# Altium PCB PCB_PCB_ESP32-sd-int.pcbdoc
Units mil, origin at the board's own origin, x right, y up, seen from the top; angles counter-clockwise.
Board outline 4345.15 x 3059.05 mil, 4 copper layers (Top Layer, Inner1, Inner2, Bottom Layer); 53 components, 39 nets, 233 pads, 78 vias.
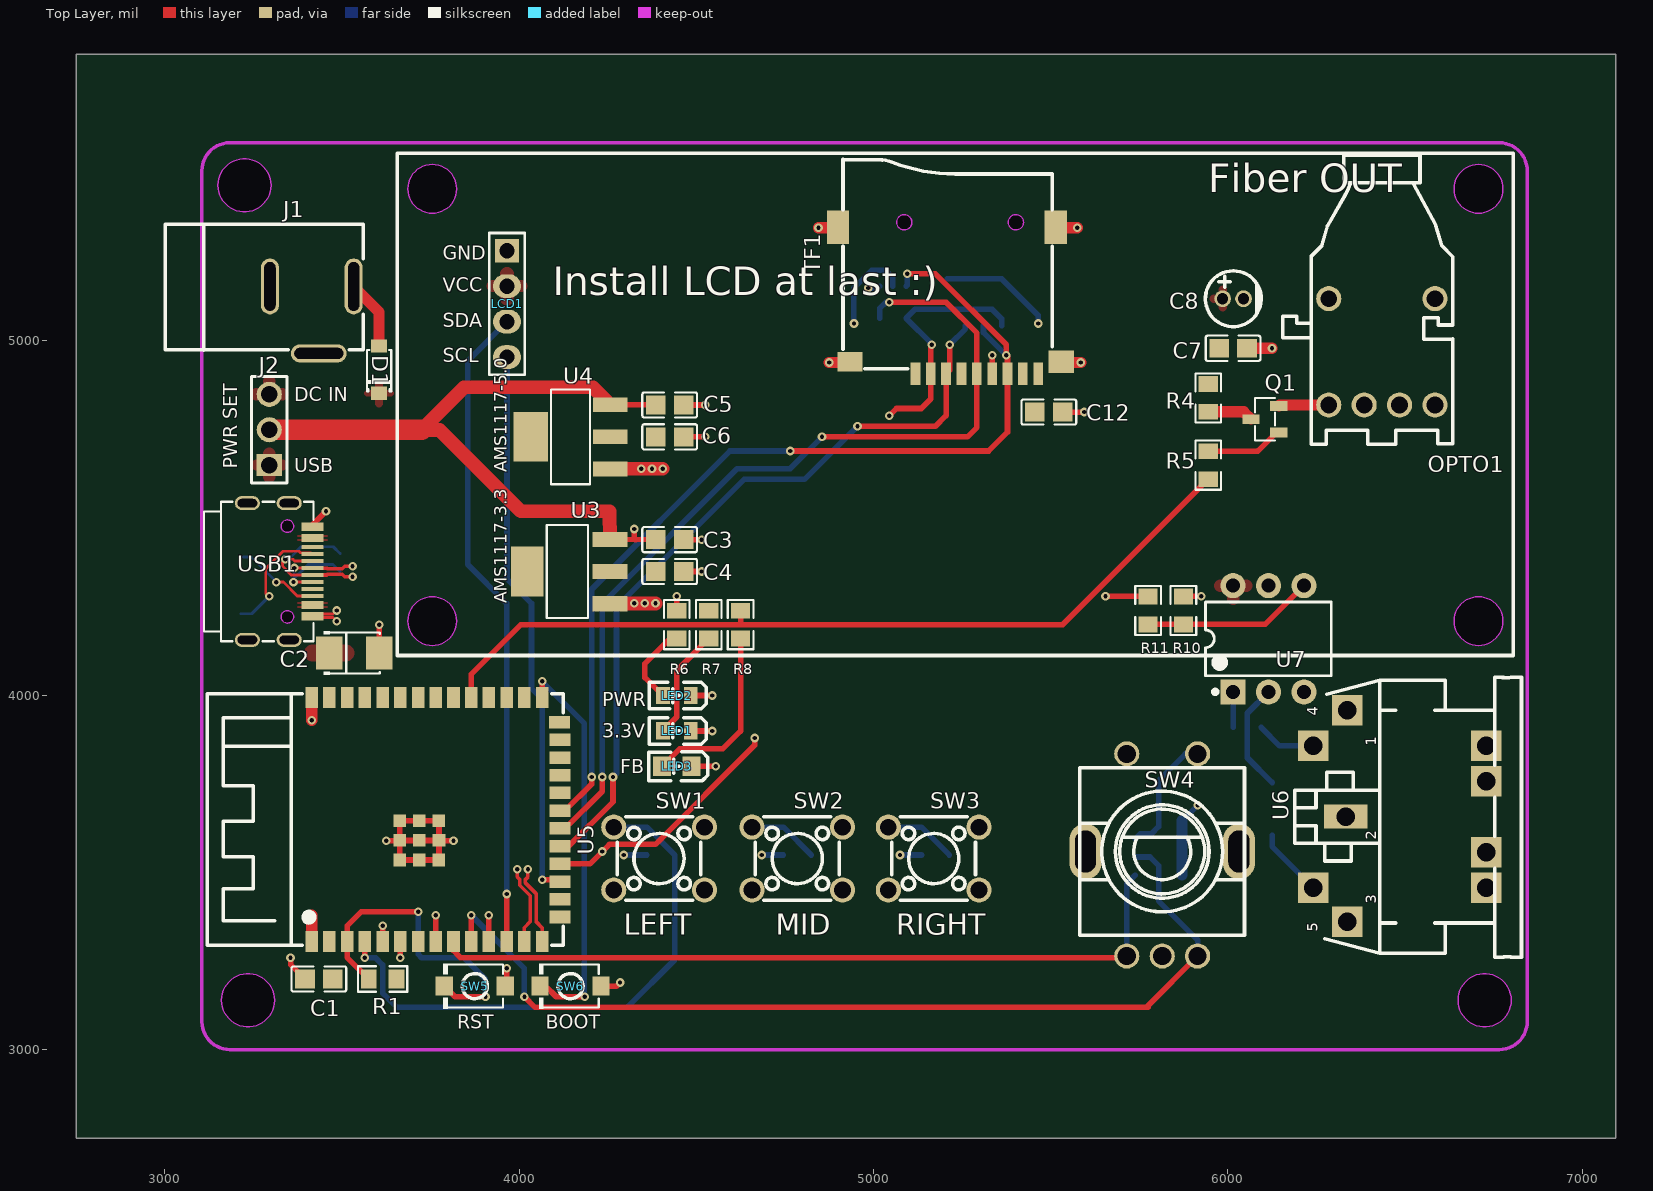
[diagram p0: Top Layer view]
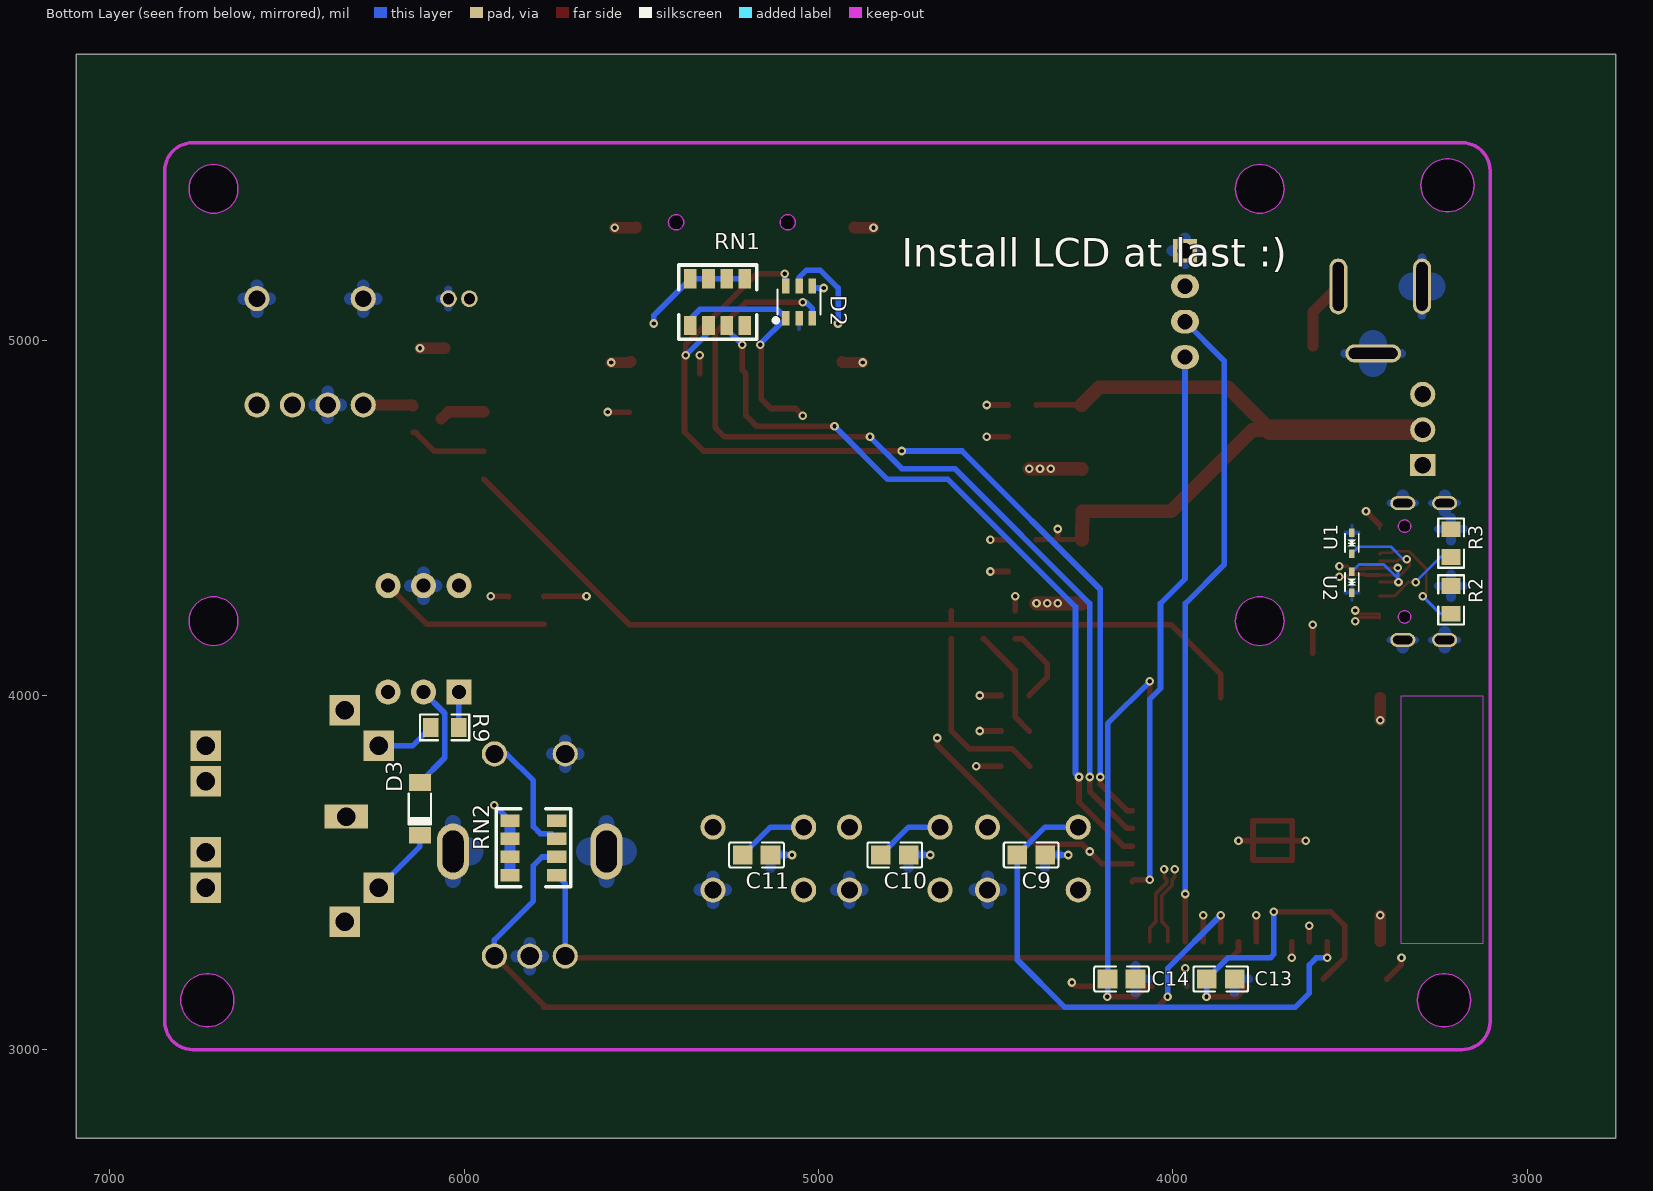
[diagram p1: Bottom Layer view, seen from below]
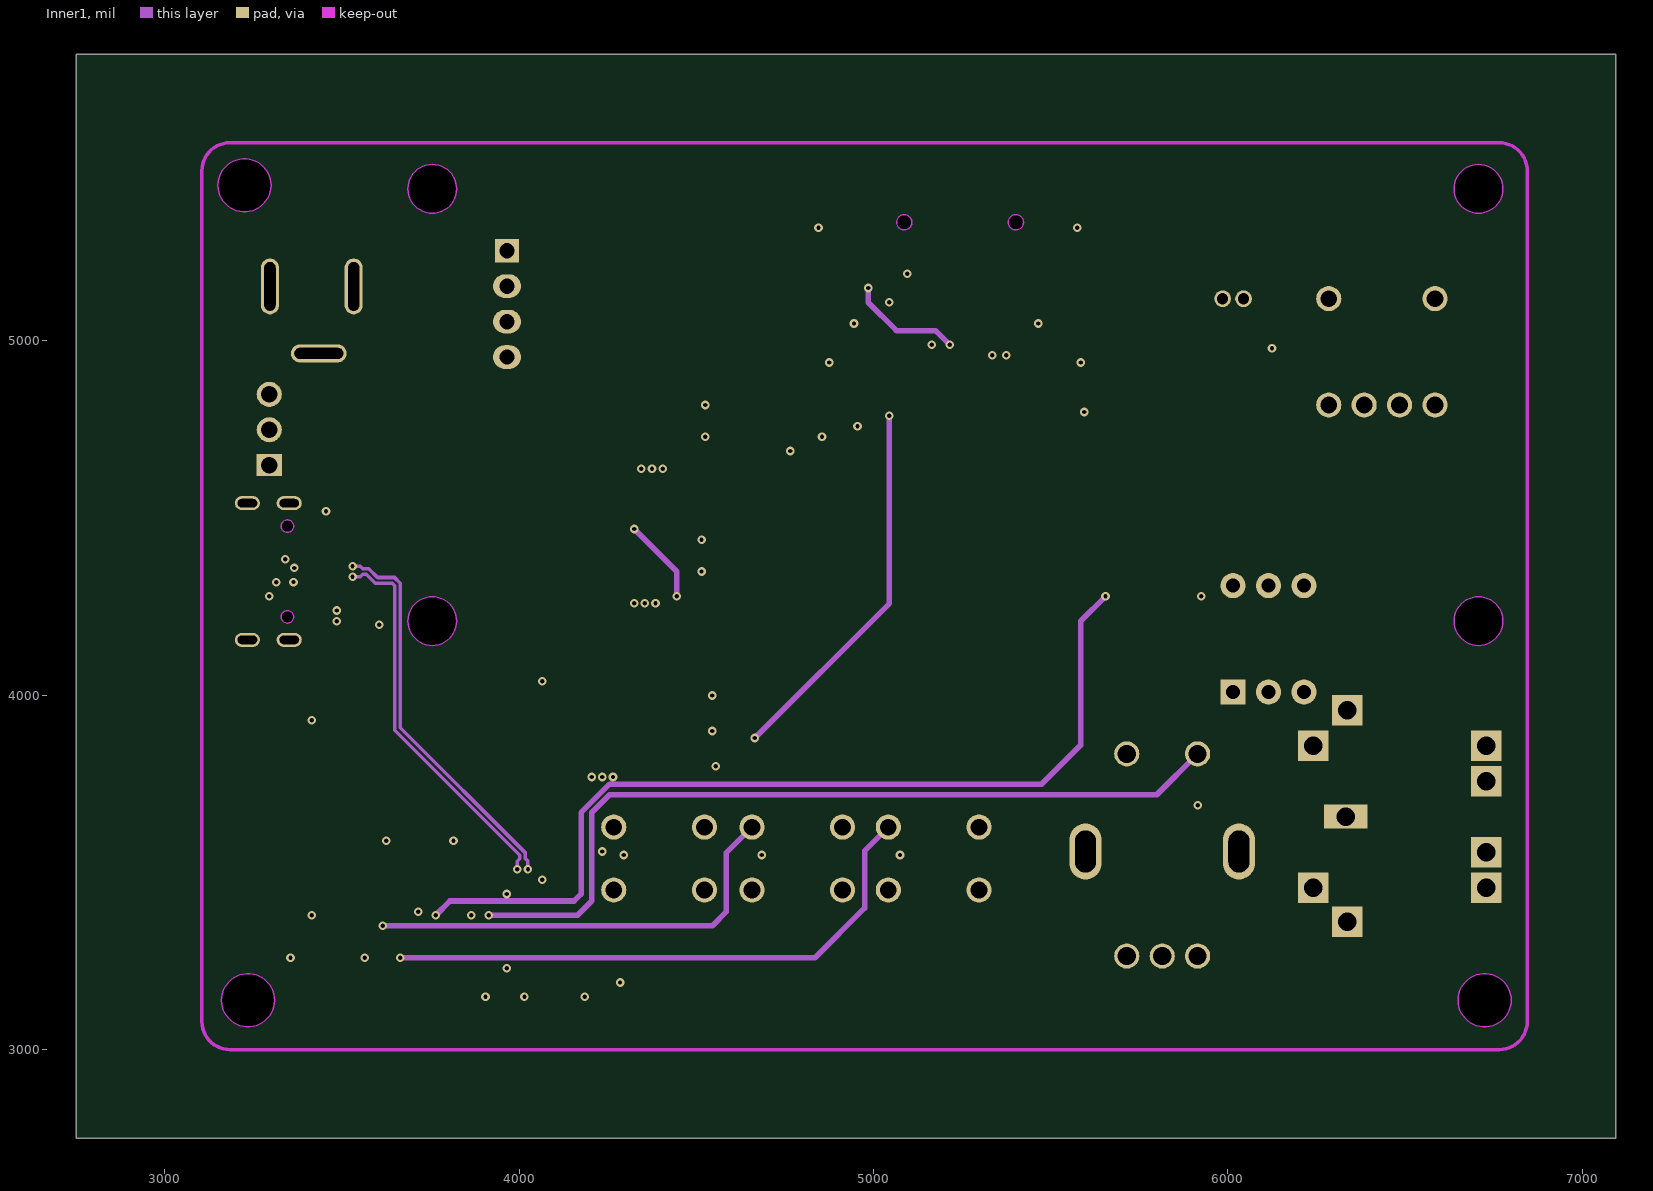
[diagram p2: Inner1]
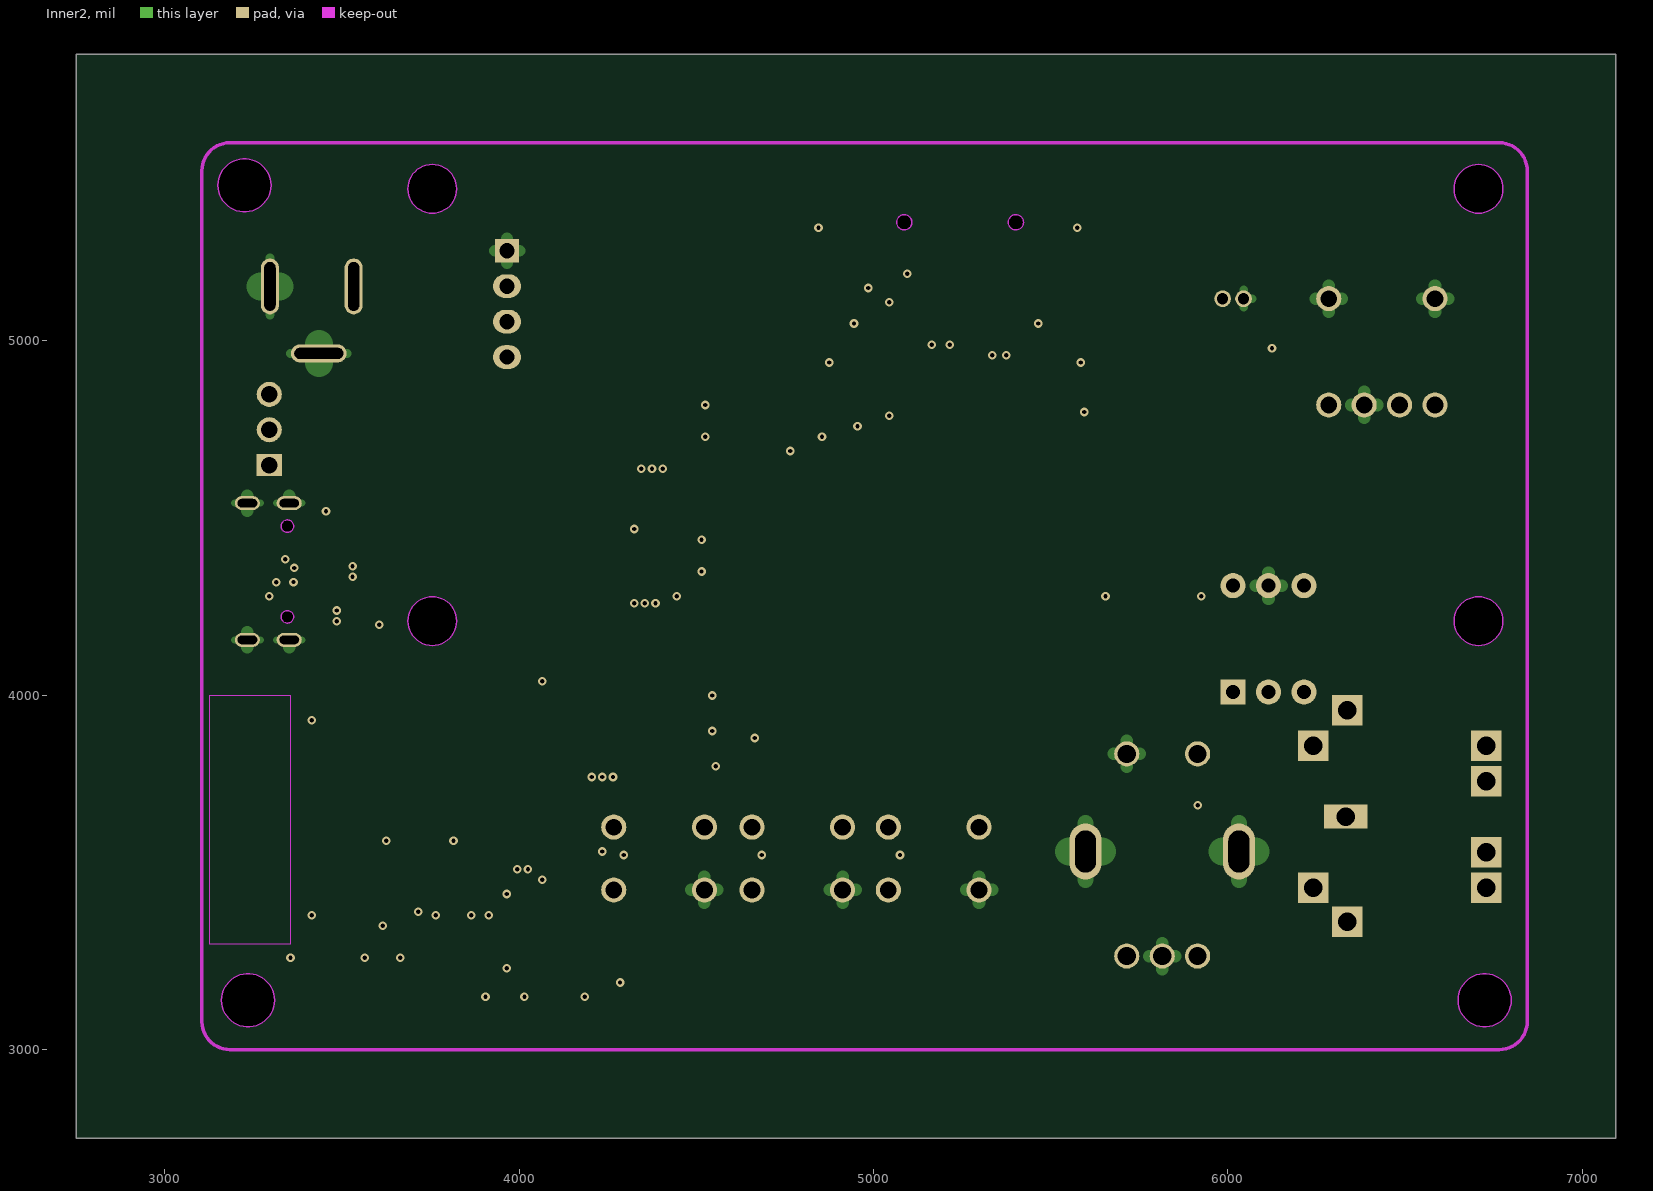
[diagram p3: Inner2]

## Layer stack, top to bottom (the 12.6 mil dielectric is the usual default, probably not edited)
Top Layer: signal copper (thickness not stored)
Dielectric: dielectric 12.6, FR-4, Dk 4.8
Inner1: signal copper (thickness not stored)
Dielectric: dielectric 12.6, FR-4, Dk 4.8
Inner2: signal copper (thickness not stored)
Dielectric: dielectric 12.6, FR-4, Dk 4.8
Bottom Layer: signal copper (thickness not stored)

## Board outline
7095.15,2750 2750,2750 2750,5809.05 7095.15,5809.05
cut-out: 3300,5439.05 cw(c3225,5439.05) 3150,5439.05 cw(c3225,5439.05)
cut-out: 6799.99,3139.05 cw(c6724.99,3139.05) 6649.99,3139.05 cw(c6724.99,3139.05)
cut-out: 3310,3139.05 cw(c3235,3139.05) 3160,3139.05 cw(c3235,3139.05)

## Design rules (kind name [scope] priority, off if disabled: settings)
BoardOutlineClearance Default [All] p0: genericclearance=10 ignorepadtopadclearanceinfootprint=FALSE except(0: Region-CutoutEdge Arc-SplitContinuation Track-SplitContinuation SMDPad-SplitContinuation THPad-SplitContinuation Via-SplitContinuation Fill-SplitContinuation Poly-SplitContinuation Region-SplitContinuation Text-SplitContinuation; 3.9: Track-OutlineEdge SMDPad-OutlineEdge THPad-OutlineEdge Via-OutlineEdge Fill-OutlineEdge Region-OutlineEdge Poly-OutlineEdge Text-OutlineEdge Track-CutoutEdge SMDPad-CutoutEdge THPad-CutoutEdge Via-CutoutEdge Fill-CutoutEdge)
Clearance Default [(InNet('GND') OR InNet('VBUS') OR InNet('J2_3') OR InNet('+3.3V') OR InNet('+5V') OR InNet('ENC_A') OR InNet('ENC_B') OR InNet('ENC_SW') OR InNet('U6_5') OR InNet('U7_2') OR InNet('U6_4') OR InNet('U7_1') OR InNet('BTN3') OR InNet('BTN2') OR InNet('BTN1') OR InNet('SCLK') OR InNet('CLK') OR InNet('MOSI') OR InNet('SDA') OR InNet('CHIP_EN') OR InNet('MISO') OR InNet('USB_P') OR InNet('USB_N') OR InNet('CS') OR InNet('USB1_A5') OR InNet('USB1_B5') OR InNet('IO0') OR InNet('VSET') OR InNet('MIDI_RX') OR InNet('VIN') OR InNet('OPTO1_1') OR InNet('Q1_3') OR InNet('Q1_1') OR InNet('LED1_2') OR InNet('LED3_1') OR InNet('LED2_2') OR InNet('U7_4') OR InNet('FB') OR InNet('MT'))] p1: gap=7 ignorepadtopadclearanceinfootprint=FALSE except(0: Region-Region; 3.9: Track-Track Track-SMDPad SMDPad-SMDPad Track-THPad SMDPad-THPad THPad-THPad Track-Via SMDPad-Via THPad-Via Via-Via Track-Fill SMDPad-Fill THPad-Fill Via-Fill Fill-Fill Track-Region SMDPad-Region THPad-Region Via-Region Fill-Region Track-Poly SMDPad-Poly THPad-Poly Via-Poly Fill-Poly Region-Poly Poly-Poly Track-Text SMDPad-Text THPad-Text Via-Text Fill-Text Region-Text Poly-Text Text-Text Track-Sheet SMDPad-Sheet THPad-Sheet Via-Sheet Fill-Sheet Region-Sheet Poly-Sheet Text-Sheet Track-Hole SMDPad-Hole THPad-Hole Via-Hole Fill-Hole Region-Hole Poly-Hole Text-Hole Sheet-Hole)
DiffPairsRouting differentialPair [All] p1: maxuncoupledlength=10 minlimit=6 maxlimit=6 mostfreqgap=6 toplayer_minwidth=5 toplayer_prefwidth=10 toplayer_maxwidth=100 bottomlayer_minwidth=5 bottomlayer_prefwidth=10 bottomlayer_maxwidth=100 midlayer1_minwidth=5 midlayer1_prefwidth=10 midlayer1_maxwidth=100 midlayer2_minwidth=5 midlayer2_prefwidth=10 midlayer2_maxwidth=100
PasteMaskExpansion Common [All] p1: expansion=0
PlaneConnect Default [All] p1: planeconnectstyle=Relief reliefexpansion=20 reliefentries=4 reliefconductorwidth=0 reliefairgap=10
PolygonConnect Default [All] p1: connectstyle=Relief reliefentries=4 reliefconductorwidth=0 polygonreliefangle="90 Angle" airgapwidth=10
PolygonConnect gge9877 [All] p1: connectstyle=Relief reliefentries=4 reliefconductorwidth=0 polygonreliefangle="90 Angle" airgapwidth=10
PolygonConnect gge9877(1) [All] p1: connectstyle=Relief reliefentries=4 reliefconductorwidth=0 polygonreliefangle="90 Angle" airgapwidth=10
PolygonConnect gge17314 [All] p1: connectstyle=Relief reliefentries=4 reliefconductorwidth=0 polygonreliefangle="90 Angle" airgapwidth=10
PolygonConnect gge17404 [All] p1: connectstyle=Relief reliefentries=4 reliefconductorwidth=0 polygonreliefangle="90 Angle" airgapwidth=10
PolygonConnect gge17428 [All] p1: connectstyle=Direct reliefentries=4 reliefconductorwidth=0 polygonreliefangle="90 Angle" airgapwidth=7.87
PolygonConnect gge21029 [All] p1: connectstyle=Direct reliefentries=4 reliefconductorwidth=0 polygonreliefangle="90 Angle" airgapwidth=10
RoutingVias Default [All] p1: viastyle="Through Hole" holewidth=12.008 minholewidth=12.008 maxholewidth=2362 width=24.016 minwidth=24.016 maxwidth=3938
SolderMaskExpansion Common [All] p1: useseparateexpansions=TRUE expansion=2 expansionbottom=2
Width Default [All] p1: maxlimit=1000 minlimit=10 preferedwidth=10

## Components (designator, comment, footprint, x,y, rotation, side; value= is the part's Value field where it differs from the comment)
C1 "100nF" C0805 3435,3199.05 r0 top
C2 "10uF" CAP-SMD_L3.2-W2.8-FD 3535,4119.05 r0 top
C3 "10uF" C0805 4425,4439.05 r180 top
C4 "10uF" C0805 4425,4349.05 r180 top
C5 "10uF" C0805 4425,4819.05 r180 top
C6 "10uF" C0805 4425,4729.05 r180 top
C7 "100nF" C0805 6014.99,4979.05 r0 top
C8 "10uF" CAP-TH_BD4.0-P1.50-D0.8-FD 6014.99,5119.05 r0 top
C9 "100nF" C0805 4400,3549.05 r0 bottom
C10 "100nF" C0805 4785,3549.05 r0 bottom
C11 "100nF" C0805 5175,3549.05 r0 bottom
C12 "100nF" C0805 5495,4799.05 r0 top
C13 "100nF" C0805 3865,3199.05 r0 bottom
C14 "100nF" C0805 4145,3199.05 r0 bottom
D1 "DSS34" SOD-123_L2.8-W1.8-LS3.7-RD 3605,4919.05 r90 top
D2 "BV-SRV05-4" SOT-23-6_L2.9-W1.6-P0.95-LS2.8-BL 5055,5109.05 r180 bottom
D3 "1N4148-1206D" LL-34_L3.5-W1.5-R-RD 6124.99,3679.05 r90 bottom
J1 "9V Battery" DC-IN-TH_DC-5520-1 3415,5059.05 r0 top
J2 "Power settings" HDR-TH_3P-P2.54-V-M-1 3295,4749.05 r90 top
LCD1 "I2CLCD16X2" I2CLCD16X2 3755,4209.05 r0 top locked
LED1 "0805 SF-RED" LED0805-RD_RED 4445.03,3899.05 r180 top
LED2 "SF-RED" LED0805-RD_RED 4445.03,3999.05 r180 top
LED3 "YLED0805G" LED0805-FD-GREEN 4444.95,3799.1 r0 top
OPTO1 "FT10MHNR_C17216617" CONN-TH_HFBR-1521Z 6434.99,4969.05 r180 top
Q1 "SS8050S" SOT-23-3_L2.9-W1.3-P0.95-LS2.4-BR 6104.99,4779.05 r0 top
R1 "10kΩ" R0805 3615,3199.05 r0 top
R2 "5.1kΩ" R0805 3215,4269.05 r270 bottom
R3 "5.1kΩ" R0805 3215,4429.05 r270 bottom
R4 "33Ω" R0805 5945,4839.05 r90 top
R5 "470Ω" R0805 5945,4649.05 r90 top
R6 "10kΩ" R0805 4445,4199.05 r90 top
R7 "1.3kΩ" R0805 4535,4199.05 r90 top
R8 "2.2kΩ" R0805 4625,4199.05 r270 top
R9 "220Ω" R0805 6054.99,3909.05 r180 bottom
R10 "180Ω" R0805 5874.99,4239.05 r270 top
R11 "47Ω" R0805 5775,4239.05 r90 top
RN1 "10kΩ" RES-ARRAY-SMD_1206-8P-L5.1-W3.1-BL 5285,5109.05 r180 bottom
RN2 "10kΩ" RES-ARRAY-SMD_1206-8P-L5.1-W3.1-BL 5805,3569.05 r90 bottom
SW1 "TC-6610-18.0" SW-TH_4P-L6.0-W6.0-P4.50-LS6.5 4395,3539.05 r0 top
SW2 "TC-6610-18.0" SW-TH_4P-L6.0-W6.0-P4.50-LS6.5 4785,3539.05 r0 top
SW3 "TC-6610-18.0" SW-TH_4P-L6.0-W6.0-P4.50-LS6.5 5170,3539.05 r0 top
SW4 "EC11E18244A5" SW-TH_EC11E18244A5 5815,3549.05 r0 top
SW5 "TS-1088-AR02016" SW-SMD_L3.9-W3.0-P4.45 3875,3179.05 r180 top
SW6 "TS-1088-AR02016" SW-SMD_L3.9-W3.0-P4.45 4145,3179.05 r180 top
TF1 "SD" TF-SMD_TF-15-15 5215,5114.05 r90 top
U1 "LESD5D5.0CT1G_C5246195" SOD-523_L1.2-W0.8-LS1.6-BI 3495,4429.05 r270 bottom
U2 "LESD5D5.0CT1G_C5246195" SOD-523_L1.2-W0.8-LS1.6-BI 3495,4319.05 r90 bottom
U3 "AMS1117-3.3" SOT-223-3_L6.5-W3.4-P2.30-LS7.0-BR 4140.04,4349.05 r0 top
U4 "AMS1117-5.0" SOT-223_L6.5-W3.5-P2.30-LS7.0-BR 4145,4729.05 r0 top
U5 "ESP32-S3-WROOM-1(N8R8)" WIRELM-SMD_ESP32-S3-WROOM-1 3765,3649.05 r90 top
U6 "MIDIJACK" CP-2350 6484.99,3659.05 r90 top
U7 "H11L1" DIP-6_L8.5-W6.4-P2.54-LS7.6-BL 6114.99,4159.05 r0 top
USB1 "MUP-U20409-2" USB-C-SMD_MUP-U20409-2 3325,4349.05 r270 top

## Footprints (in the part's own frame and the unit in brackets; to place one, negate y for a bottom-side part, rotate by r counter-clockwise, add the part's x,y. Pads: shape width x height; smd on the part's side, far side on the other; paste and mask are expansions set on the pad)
C0805 [mm]
  rect 1.41x1.35 smd: 1(-1,0) 2(1,0)
  silkscreen extent -1.96,-0.9 1.96,0.9
CAP-SMD_L3.2-W2.8-FD [mm]
  rect 1.9x2.376 smd: 1(-1.799,0) 2(1.799,0)
  silkscreen extent -2.21,-1.55 1.83,1.55
CAP-TH_BD4.0-P1.50-D0.8-FD [mm]
  round 1.2 hole 0.8: 1(-0.75,0) 2(0.75,0)
  silkscreen extent -1.98,-2 2.06,2
CONN-TH_HFBR-1521Z [mm]
  round 1.8 hole 1.2: 1(3.81,3.81) 2(1.27,3.81) 3(-1.27,3.81) 4(-3.81,3.81) 5(-3.81,-3.81) 8(3.81,-3.81)
  silkscreen extent -5.08,-14.11 7.11,6.61
CP-2350 [mil]
  rect 86x86 hole 52: 1(297.99,148) 3(-298.01,148) 4(197.99,244) 5(-202.01,244) PE(-102.01,-244) PE1(-202.01,-244) PE2(197.99,-244) PE@(97.99,-244)
  rect 67.7x121.9 hole 52: 2(-2.01,152)
  silkscreen extent -398,-344 391,296
DC-IN-TH_DC-5520-1 [mm]
  oval 4x1.3 hole 0.8 slot 3.5 at 0 deg copper offset 0,0: 2(0.5,-2.4)
  oval 1.3x4 hole 0.8 slot 3.5 at 90 deg: 3(-3,2.4) 4(3,2.4)
  silkscreen extent -10.5,-2.16 3.7,6.85
DIP-6_L8.5-W6.4-P2.54-LS7.6-BL [mm]
  rect 1.8x1.8 hole 1: 1(-2.54,-3.81)
  round 1.8 hole 1: 2(0,-3.81) 3(2.54,-3.81) 4(2.54,3.81) 5(0,3.81) 6(-2.54,3.81)
  silkscreen extent -4.52,-3.95 4.5,2.65
HDR-TH_3P-P2.54-V-M-1 [mm]
  rect 1.575x1.8 hole 1.2: 1(-2.54,0)
  round 1.8 hole 1.2: 2(0,0) 3(2.54,0)
  silkscreen extent -3.81,-1.27 3.81,1.27
I2CLCD16X2 [mm]
  rect 1.7x1.7 hole 1.1: 1(5.359,26.549)
  oval 2x1.7 hole 1.1: 2(5.359,24.009) 3(5.359,21.469) 4(5.359,18.929)
  Board Outline Layer circle w0.005: c75,30.988 r1.75
  Board Outline Layer circle w0.005: c75,0 r1.75
  Board Outline Layer circle w0.005: c0,0 r1.75
  Board Outline Layer circle w0.005: c0,30.988 r1.75
  Board Outline Layer region: 76.75,30.988 76.577,30.229 76.091,29.62 75.389,29.282 74.61,29.282 73.909,29.62 73.423,30.229 73.25,30.988 73.25,30.988 73.423,31.747 73.909,32.356 74.61,32.694 75.389,32.694 76.091,32.356 76.577,31.747 76.75,30.988
  Board Outline Layer region: 76.75,0 76.577,-0.759 76.091,-1.368 75.389,-1.706 74.61,-1.706 73.909,-1.368 73.423,-0.759 73.25,0 73.25,0 73.423,0.759 73.909,1.368 74.61,1.706 75.389,1.706 76.091,1.368 76.577,0.759 76.75,0
  Board Outline Layer region: 1.75,0 1.577,-0.759 1.091,-1.368 0.389,-1.706 -0.389,-1.706 -1.091,-1.368 -1.577,-0.759 -1.75,0 -1.75,0 -1.577,0.759 -1.091,1.368 -0.389,1.706 0.389,1.706 1.091,1.368 1.577,0.759 1.75,0
  Board Outline Layer region: 1.75,30.988 1.577,30.229 1.091,29.62 0.389,29.282 -0.389,29.282 -1.091,29.62 -1.577,30.229 -1.75,30.988 -1.75,30.988 -1.577,31.747 -1.091,32.356 -0.389,32.694 0.389,32.694 1.091,32.356 1.577,31.747 1.75,30.988
  Multi-Layer board cut-out: 76.75,30.988 76.577,30.229 76.091,29.62 75.389,29.282 74.61,29.282 73.909,29.62 73.423,30.229 73.25,30.988 73.25,30.988 73.423,31.747 73.909,32.356 74.61,32.694 75.389,32.694 76.091,32.356 76.577,31.747 76.75,30.988
  Multi-Layer board cut-out: 76.75,0 76.577,-0.759 76.091,-1.368 75.389,-1.706 74.61,-1.706 73.909,-1.368 73.423,-0.759 73.25,0 73.25,0 73.423,0.759 73.909,1.368 74.61,1.706 75.389,1.706 76.091,1.368 76.577,0.759 76.75,0
  Multi-Layer board cut-out: 1.75,0 1.577,-0.759 1.091,-1.368 0.389,-1.706 -0.389,-1.706 -1.091,-1.368 -1.577,-0.759 -1.75,0 -1.75,0 -1.577,0.759 -1.091,1.368 -0.389,1.706 0.389,1.706 1.091,1.368 1.577,0.759 1.75,0
  Multi-Layer board cut-out: 1.75,30.988 1.577,30.229 1.091,29.62 0.389,29.282 -0.389,29.282 -1.091,29.62 -1.577,30.229 -1.75,30.988 -1.75,30.988 -1.577,31.747 -1.091,32.356 -0.389,32.694 0.389,32.694 1.091,32.356 1.577,31.747 1.75,30.988
  silkscreen extent -2.51,-2.47 77.49,33.53
LED0805-FD-GREEN [mil]
  rect 51.2x55.1 smd: 1(-41.35,0) 2(41.35,0)
  silkscreen extent -78,-40 88,41
LED0805-RD_RED [mm]
  rect 1x1.25 smd: 1(-1,0) 2(1,0)
  silkscreen extent -2.1,-0.95 1.98,0.96
LL-34_L3.5-W1.5-R-RD [mm]
  rect 1.185x1.566 smd: 1(1.892,0) 2(-1.892,0)
  silkscreen extent -1.1,-0.8 1.1,0.8
R0805 [mil]
  rect 44.59x54.21 smd: 1(-39.37,0) 2(39.37,0)
  silkscreen extent -69,-36 69,36
RES-ARRAY-SMD_1206-8P-L5.1-W3.1-BL [mm]
  rect 0.9x1.37 smd: 1(-1.95,-1.68) 2(-0.65,-1.68) 3(0.65,-1.68) 4(1.95,-1.68) 5(1.95,1.68) 6(0.65,1.68) 7(-0.65,1.68) 8(-1.95,1.68)
  silkscreen extent -2.79,-2.67 2.79,2.67
SOD-123_L2.8-W1.8-LS3.7-RD [mm]
  rect 0.95x1.15 smd: 1(-1.692,0) 2(1.692,0)
  silkscreen extent -1.58,-0.87 1.41,0.87
SOD-523_L1.2-W0.8-LS1.6-BI [mm]
  rect 0.6x0.4 smd: 1(-0.75,0) 2(0.75,0)
  silkscreen extent -0.65,-0.5 0.65,0.5
SOT-23-3_L2.9-W1.3-P0.95-LS2.4-BR [mm]
  rect 1.25x0.7 smd: 1(1,-0.95) 2(1,0.95) 3(-1,0)
  silkscreen extent -0.73,-1.53 0.73,1.53
SOT-23-6_L2.9-W1.6-P0.95-LS2.8-BL [mil]
  rect 20.95x42.2 smd: 1(-37.4,-45.24) 2(0,-45.24) 3(37.4,-45.24) 4(37.4,45.24) 5(0,45.24) 6(-37.4,45.24)
  silkscreen extent -72,-57 61,35
SOT-223-3_L6.5-W3.4-P2.30-LS7.0-BR [mm]
  rect 2.5x1.1 smd: 1(2.97,-2.3) 2(2.97,0) 3(2.97,2.3)
  rect 2.34x3.6 smd: 4(-2.97,0)
  silkscreen extent -1.57,-3.33 1.37,3.33
SOT-223_L6.5-W3.5-P2.30-LS7.0-BR [mm]
  rect 2.465x1.05 smd: 1(2.858,-2.3) 2(2.858,0) 3(2.858,2.3)
  rect 2.465x3.54 smd: 4(-2.857,0)
  silkscreen extent -1.4,-3.4 1.4,3.4
SW-SMD_L3.9-W3.0-P4.45 [mm]
  rect 1.23x1.36 smd: 1(-2.185,0) 2(2.185,0)
  silkscreen extent -2.03,-1.62 2.25,1.62
SW-TH_4P-L6.0-W6.0-P4.50-LS6.5 [mm]
  round 1.8 hole 1.2 copper offset 0,0: 1(-3.25,2.25)
  round 1.8 hole 1.2: 2(3.25,2.25) 3(-3.25,-2.25) 4(3.25,-2.25)
  silkscreen extent -3,-3 3,3
SW-TH_EC11E18244A5 [mm]
  oval 2.3x4 hole 1.5 slot 3 at 90 deg: 6(5.5,0.25) 7(-5.5,0.25)
  round 1.8 hole 1.3: A(-2.54,-7.25) B(2.54,-7.25) C(0,-7.25) D(-2.54,7.25) E(2.54,7.25)
  silkscreen extent -5.9,-5.75 5.9,6.25
TF-SMD_TF-15-15 [mil]
  rect 63x27.6 smd: 1(-206.75,96.45) 2(-206.75,53.15) 3(-206.75,9.84) 4(-206.75,-33.47) 5(-206.75,-76.77) 6(-206.75,-120.08) 7(-206.75,-163.39) 8(-206.75,-206.7) 9(-206.75,-250)
  rect 63x70.87 smd: 10(-173.17,-314.96)
  rect 94.49x62.99 smd: 11(206.75,-299.22) 12(206.75,314.96)
  rect 55.1x70.9 smd: 13(-173.15,281.51)
  Board Outline Layer circle w0.2: c220.53,-187 r21.65
  Board Outline Layer circle w0.2: c220.53,128 r21.65
  Board Outline Layer region: 220.53,-208.65 211.13,-206.51 203.6,-200.5 199.42,-191.82 199.42,-182.18 203.6,-173.5 211.13,-167.49 220.53,-165.35 220.53,-165.35 229.93,-167.49 237.46,-173.5 241.64,-182.18 241.64,-191.82 237.46,-200.5 229.93,-206.51 220.53,-208.65
  Board Outline Layer region: 220.53,106.35 211.13,108.49 203.6,114.5 199.42,123.18 199.42,132.82 203.6,141.5 211.13,147.51 220.53,149.65 220.53,149.65 229.93,147.51 237.46,141.5 241.64,132.82 241.64,123.18 237.46,114.5 229.93,108.49 220.53,106.35
  Multi-Layer board cut-out: 220.53,-208.65 211.13,-206.51 203.6,-200.5 199.42,-191.82 199.42,-182.18 203.6,-173.5 211.13,-167.49 220.53,-165.35 220.53,-165.35 229.93,-167.49 237.46,-173.5 241.64,-182.18 241.64,-191.82 237.46,-200.5 229.93,-206.51 220.53,-208.65
  Multi-Layer board cut-out: 220.53,106.35 211.13,108.49 203.6,114.5 199.42,123.18 199.42,132.82 203.6,141.5 211.13,147.51 220.53,149.65 220.53,149.65 229.93,147.51 237.46,141.5 241.64,132.82 241.64,123.18 237.46,114.5 229.93,108.49 220.53,106.35
  silkscreen extent -193,-290 398,301
USB-C-SMD_MUP-U20409-2 [mm]
  oval 1x1.8 hole 0.6 slot 1.4 at 90 deg: 17(4.9,0.668) 18(4.9,-2.333) 19(-4.9,-2.333) 20(-4.9,0.667)
  rect 0.3x1.55 smd: A1(-3.35,2.332) A4(-2.55,2.332) A5(-1.25,2.332) A6(-0.25,2.332) A7(0.25,2.332) A8(1.25,2.332) A9(2.55,2.332) A12(3.35,2.332) B1(3.05,2.332) B4(2.25,2.332) B5(1.75,2.332) B6(0.75,2.332) B7(-0.75,2.332) B8(-1.75,2.332) B9(-2.25,2.332) B12(-3.05,2.332)
  Board Outline Layer circle w0.005: c-3.25,0.533 r0.45
  Board Outline Layer circle w0.005: c3.25,0.533 r0.45
  Board Outline Layer region: -3.25,0.983 -3.055,0.939 -2.898,0.814 -2.811,0.634 -2.811,0.433 -2.898,0.253 -3.055,0.128 -3.25,0.083 -3.25,0.083 -3.445,0.128 -3.602,0.253 -3.689,0.433 -3.689,0.634 -3.602,0.814 -3.445,0.939 -3.25,0.983
  Board Outline Layer region: 3.25,0.983 3.445,0.939 3.602,0.814 3.689,0.634 3.689,0.433 3.602,0.253 3.445,0.128 3.25,0.083 3.25,0.083 3.055,0.128 2.898,0.253 2.811,0.433 2.811,0.634 2.898,0.814 3.055,0.939 3.25,0.983
  Multi-Layer board cut-out: -3.25,0.983 -3.055,0.939 -2.898,0.814 -2.811,0.634 -2.811,0.433 -2.898,0.253 -3.055,0.128 -3.25,0.083 -3.25,0.083 -3.445,0.128 -3.602,0.253 -3.689,0.433 -3.689,0.634 -3.602,0.814 -3.445,0.939 -3.25,0.983
  Multi-Layer board cut-out: 3.25,0.983 3.445,0.939 3.602,0.814 3.689,0.634 3.689,0.433 3.602,0.253 3.445,0.128 3.25,0.083 3.25,0.083 3.055,0.128 2.898,0.253 2.811,0.433 2.811,0.634 2.898,0.814 3.055,0.939 3.25,0.983
  silkscreen extent -5,-5.43 5,2.42
WIRELM-SMD_ESP32-S3-WROOM-1 [mm]
  rect 1.5x0.9 smd: 1(-8.75,8.895) 2(-8.75,7.625) 3(-8.75,6.355) 4(-8.75,5.085) 5(-8.75,3.815) 6(-8.75,2.545) 7(-8.75,1.275) 8(-8.75,0.005) 9(-8.75,-1.265) 10(-8.75,-2.535) 11(-8.75,-3.805) 12(-8.75,-5.075) 13(-8.75,-6.345) 14(-8.75,-7.615) 27(8.75,-7.615) 28(8.75,-6.345) 29(8.75,-5.075) 30(8.75,-3.805) 31(8.75,-2.535) 32(8.75,-1.265) 33(8.75,0.005) 34(8.75,1.275) 35(8.75,2.545) 36(8.75,3.815) 37(8.75,5.085) 38(8.75,6.355) 39(8.75,7.625) 40(8.75,8.895)
  rect 0.9x1.5 smd: 15(-6.985,-8.895) 16(-5.715,-8.895) 17(-4.445,-8.895) 18(-3.175,-8.895) 19(-1.905,-8.895) 20(-0.635,-8.895) 21(0.635,-8.895) 22(1.905,-8.895) 23(3.175,-8.895) 24(4.445,-8.895) 25(5.715,-8.895) 26(6.985,-8.865)
  rect 0.9x0.9 smd: 41(-2.9,-0.225) 41(-2.9,1.175) 41(-2.9,2.575) 41(-1.5,2.575) 41(-1.5,-0.225) 41(-1.5,1.175) 41(-0.1,2.575) 41(-0.1,1.175) 41(-0.1,-0.225)
  silkscreen extent -9,-9.14 9.02,16.39

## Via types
v1: diameter 24.41, hole 12.2, Top Layer to Bottom Layer, 73 vias
v2: diameter 24.02, hole 12.01, Top Layer to Bottom Layer, 5 vias

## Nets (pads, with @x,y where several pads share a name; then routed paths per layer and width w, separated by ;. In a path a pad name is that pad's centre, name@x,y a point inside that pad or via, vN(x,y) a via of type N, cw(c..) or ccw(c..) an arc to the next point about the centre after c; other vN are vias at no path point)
+3.3V: C1.2 C4.2 C12.1 D2.5 R1.2 R7.2 R10.1 RN1.5 RN1.6 RN1.7 RN1.8 RN2.5 RN2.6 RN2.7 RN2.8 TF1.4 U3.2 U3.4 U5.2 U7.6 | length 851.3
  Top Layer w15.83: R10.1 v1(5925,4279.05)
  Bottom Layer w15.83: v1@4945,5049.05 4945,5149.05 4995,5199.05 5035,5199.05 5055,5179.05 D2.5 ; RN1.5 RN1.8 5465,5071.97 v1@5465,5049.05 ; RN2.5 v1(5915,3689.05)
  Bottom Layer w31.61: RN2.8 RN2.7 RN2.6 RN2.5
  other v1: 4945,5049.05 5465,5049.05
+5V: C6.2 C7.1 C8.1 LCD1.2 R4.2 U4.2 U4.4
BTN1: C9.2 SW1.1 U5.4 | length 1581.1
  Top Layer w15.83: v1@3564.8,3259.05 U5.4
  Bottom Layer w15.83: v1(3564.8,3259.05) 3595.01,3259.05 3615,3239.05 3615,3159.05 3655,3119.05 4305,3119.05 4439.37,3253.43 C9.2 4360.79,3627.63 SW1.1@4267.05,3627.63
BTN2: C10.2 SW2.1 U5.5 | length 1499.5
  Top Layer w15.83: U5.5 v1@3614.8,3349.05
  Inner1 w15.83: v1@3614.8,3349.05 4545,3349.05 4585,3389.05 4585,3555.58 SW2.1@4657.05,3627.63
  Bottom Layer w15.83: SW2.1@4657.05,3627.63 4745.79,3627.63 C10.2
  other v1: 3614.8,3349.05
BTN3: C11.2 SW3.1 U5.6 | length 1874.7
  Top Layer w15.83: U5.6 v1(3665,3259.05)
  Inner1 w15.83: v1(3665,3259.05) 4834.99,3259.05 4975,3399.05 4975,3560.58 SW3.1@5042.05,3627.63
  Bottom Layer w15.83: SW3.1@5042.05,3627.63 5135.79,3627.63 C11.2
CHIP_EN: C13.2 R1.1 SW5.2 U5.3 | length 909
  Top Layer w15.83: R1.1 3514.81,3259.88 U5.3 3514.8,3348.86 3555,3389.05 v1(3715,3389.05) ; SW5.2 3818.97,3149.05 v1@3905,3149.05
  Bottom Layer w15.83: v1(3715,3389.05) 3715,3269.05 3725,3259.05 3844.4,3259.05 C13.2@3904.4,3199.05 ; C13.2@3904.37,3199.05 3904.37,3149.68 v1(3905,3149.05)
CLK: D2.3 TF1.5 U5.20 | length 2557.5
  Top Layer w15.83: U5.20 4129.99,3624.05 4235,3729.05 v1(4235,3769.05) ; v1(4855,4729.05) 5265,4729.05 5291.77,4755.83 TF1.5 ; v1(5045,5109.05) 5205,5109.05 5291.8,5022.25 TF1.5@5291.8,4907.25
  Bottom Layer w15.83: v1@4235,3769.05 4235,4259.05 4615,4639.05 4765,4639.05 v1(4855,4729.05) ; D2.3 5017.6,5091.65 v1@5035,5109.05
CS: D2.1 RN1.1 TF1.2 U5.18 | length 2481.8
  Top Layer w15.83: U5.18 4200,3524.05 4235,3559.05 4255,3579.05 4385,3579.05 4665,3859.05 v1(4665,3879.05) ; v1(5045,4789.05) 5065,4809.05 5135,4809.05 5161.85,4835.9 TF1.2 5161.85,4985.9 v1(5165,4989.05)
  Inner1 w15.83: v1(4665,3879.05) 5045,4259.05 v1(5045,4789.05)
  Bottom Layer w15.83: v1(5165,4989.05) 5165,4991.21 D2.1 5117.64,5089.05 5335,5089.05 5361.77,5062.28 RN1.1
  other v1: 4235,3559.05
ENC_A: RN2.1 SW4.A U5.9 | length 2174.3
  Top Layer w15.83: U5.9 3814.8,3279.25 3835,3259.05 5710.43,3259.05 SW4.A
  Bottom Layer w15.83: SW4.A 5714.99,3468.42 RN2.1
ENC_B: RN2.2 SW4.B U5.10 | length 2718.9
  Top Layer w15.83: U5.10 3864.8,3338.86 3865,3339.06 v1(3865,3379.05) ; v1@4015,3149.05 4045,3119.05 5775,3119.05 5775,3123.62 SW4.B
  Bottom Layer w15.83: v1@3865,3379.05 4015,3229.05 v1(4015,3149.05) ; RN2.2 5780.59,3543.46 5805,3519.05 5805,3419.05 5914.99,3309.06 SW4.B
ENC_SW: RN2.3 SW4.E U5.11 | length 2761.4
  Top Layer w15.83: U5.11 v1(3914.8,3379.05)
  Inner1 w15.83: v1(3914.8,3379.05) 4165,3379.05 4205,3419.05 4205,3669.05 4255,3719.05 5799.56,3719.05 SW4.E
  Bottom Layer w15.83: RN2.3 5753.27,3609.05 5785,3609.05 5805,3629.05 5805,3759.05 5880.43,3834.49 SW4.E
FB: R5.1 R8.1 U5.31 | length 2413
  Top Layer w15.83: U5.31 3864.8,4058.86 4005,4199.05 5534.37,4199.05 R5.1 ; 4625,4199.05 R8.1
GND: C1.1 C2.2 C3.1 C4.1 C5.1 C6.1 C7.2 C8.2 C9.1 C10.1 C11.1 C12.2 C13.1 C14.1 D2.2 J1.2 J1.3 LCD1.1 LED1.1 LED2.1 LED3.2 OPTO1.2 OPTO1.5 OPTO1.8 R2.1 R3.1 SW1.4 SW2.4 SW3.4 SW4.6 SW4.7 SW4.C SW4.D SW5.1 SW6.1 TF1.6 TF1.10 TF1.11 TF1.12 TF1.13 U1.1 U2.1 U3.1 U4.1 U5.1 U5.40 U5.41 U7.5 USB1.17 USB1.18 USB1.19 USB1.20 USB1.A1 USB1.A12 USB1.B1 USB1.B12 | length 2550.2
  Top Layer w7.91: USB1.B12 USB1.A1 ; v1@3485,4209.05 3475,4219.05 3418.72,4219.05 USB1.A12 USB1.B1 3474.92,4228.97 v1(3485,4239.05)
  Top Layer w15.83: v1@3355,3259.05 3355,3239.68 C1.1 ; USB1.A1 v1@3454.94,4519.05 ; v1(3605,4199.05) C2.2 ; v1(3625,3589.05) U5.41@3663.6,3589.95 ; U5.41@3773.9,3589.95 v1(3815,3589.05) ; SW5.1 3965,3183.03 v1(3965,3229.05) ; SW6.1 4275,3179.05 v1@4285,3189.05 ; C6.1@4464.37,4729.05 v1(4525,4729.05) ; C5.1@4464.37,4819.05 v1(4525,4819.05) ; C4.1 v1(4515,4349.05) ; C3.1@4464.4,4439.05 v1(4515,4439.05) ; LED1.1 v1(4545,3899.05) ; LED2.1 v1(4545,3999.05) ; LED3.2@4486.35,3799.05 v1(4555,3799.05) ; v1(5335,4959.05) TF1.6@5335.1,4907.25 ; C12.2 v1(5595,4799.05) ; U5.41@3663.62,3589.99 3718.74,3589.99 U5.41@3773.86,3589.99 ; U5.41@3663.62,3589.99 3663.62,3534.87 3718.74,3534.87 3773.86,3534.87 U5.41@3773.86,3589.99 ; U5.41@3663.62,3589.99 3663.62,3645.11 3718.74,3645.11 3773.86,3645.11 U5.41@3773.86,3589.99
  Top Layer w31.61: U5.1 v1(3414.8,3379.05) ; U5.40@3414.8,3993.55 v1(3415,3929.05) ; v1(4845,5319.05) 4898.29,5319.05 TF1.12 ; v1@4875,4939.05 4931.64,4939.05 TF1.13 ; TF1.11 5515.97,5319.05 v1(5575,5319.05) ; TF1.10 5531.79,4939.05 v1@5585,4939.05 ; C7.2 v1@6124.99,4979.05
  Top Layer w39.37: U3.1@4257,4258.05 4258,4259.05 v1(4385,4259.05) ; U4.1@4257.5,4638.55 4258,4639.05 4345,4639.05 4375,4639.05 v1@4405,4639.05
  Bottom Layer w15.83: v1@4295,3549.05 C9.1 ; v1@4685,3549.05 C10.1 ; v1@5075,3549.05 C11.1
  other v1: 4285,3189.05 3355,3259.05 4295,3549.05 4685,3549.05 5075,3549.05 3485,4209.05 4325,4259.05 4355,4259.05 3455,4519.05 4345,4639.05 4375,4639.05 4405,4639.05 4875,4939.05 5585,4939.05 6124.99,4979.05
IO0: C14.2 SW6.2 U5.27 | length 1123.7
  Top Layer w15.83: SW6.2 4075.01,3179.05 4105,3149.05 v1(4185,3149.05) ; U5.27@4064.8,3993.55 v1(4065,4039.05)
  Bottom Layer w15.83: v1(4065,4039.05) 4184.37,3919.68 4184.37,3199.05 4184.37,3149.68 v1(4185,3149.05)
J2_3: D1.1 J2.3
LED1_2: LED1.2 R7.1 | length 314
  Top Layer w15.83: LED1.2 4445,3938.35 4445,4069.05 R7.1@4535,4159.65
LED2_2: LED2.2 R6.1 | length 230.3
  Top Layer w15.83: LED2.2 4355,4049.68 4355,4089.05 4425.63,4159.68 R6.1
LED3_1: LED3.1 R8.2 | length 523.4
  Top Layer w15.83: LED3.1@4403.65,3799.05 4453.65,3849.05 4575,3849.05 4625,3899.06 R8.2
MIDI_RX: R11.2 U5.8 | length 2797.2
  Top Layer w15.83: U5.8 v1(3764.8,3379.05) ; v1@5655,4279.05 R11.2
  Inner1 w15.83: v1(3764.8,3379.05) 3804.8,3419.05 4155,3419.05 4175,3439.05 4175,3669.05 4255,3749.05 5475,3749.05 5585,3859.05 5585,4209.05 v1(5655,4279.05)
MISO: D2.6 RN1.2 TF1.7 U5.21 | length 2785.1
  Top Layer w15.83: U5.21 4129.99,3674.05 4205,3749.05 v1(4205,3769.05) ; v1(4765,4689.05) 5325,4689.05 5378.39,4742.45 TF1.7 5378.39,4955.66 5375,4959.05 5375,4989.05 5175,5189.05 v1(5095,5189.05)
  Bottom Layer w15.83: v1@4205,3769.05 4205,4299.05 4595,4689.05 v1(4765,4689.05) ; D2.6 5095,5156.89 v1@5095,5189.05 ; RN1.2 5310.59,5023.46 v1@5375,4959.05
  other v1: 5375,4959.05
MOSI: D2.4 RN1.3 TF1.3 U5.19 | length 2526.1
  Top Layer w15.83: U5.19 4139.99,3574.05 4265,3699.05 v1(4265,3769.05) ; v1(4955,4759.05) 5175,4759.05 5205.16,4789.22 TF1.3 5215,4917.14 v1(5215,4989.05)
  Inner1 w15.83: v1(4985,5149.05) 4985,5109.05 5065,5029.05 5175,5029.05 5205,4999.05
  Bottom Layer w15.83: v1@4265,3769.05 4275,3779.05 4275,4249.05 4635,4609.05 4805,4609.05 v1(4955,4759.05) ; v1(4985,5149.05) 5012.36,5149.05 D2.4 ; v1(5215,4989.05) 5259.41,5033.46 RN1.3
MT: U6.PE
OPTO1_1: OPTO1.1 Q1.2 | length 141.7
  Top Layer w31.61: Q1.2 6146.96,4819.05 OPTO1.1
Q1_1: Q1.1 R5.2 | length 221.2
  Top Layer w15.83: R5.2 6085,4689.05 6137.6,4741.65 Q1.1
Q1_3: Q1.3 R4.1 | length 129.2
  Top Layer w31.61: R4.1 6044.99,4799.68 Q1.3
SCLK: LCD1.4 U5.17 | length 1568.5
  Top Layer w15.83: v1@4065,3479.05 4110.2,3479.05 U5.17
  Bottom Layer w15.83: LCD1.4 3965.98,4328.07 4035,4259.05 4035,4019.05 4065,3989.05 v1(4065,3479.05)
SDA: LCD1.3 U5.12 | length 1841.2
  Top Layer w15.83: U5.12 v1(3964.8,3439.05)
  Bottom Layer w15.83: v1(3964.8,3439.05) 3964.8,4259.25 3855,4369.05 3855,4943.31 LCD1.3
U6_4: R9.1 U6.4 | length 168.2
  Bottom Layer w15.83: R9.1@6094.37,3909.05 6146.37,3857.05 U6.4
U6_5: D3.2 U6.5 | length 195.5
  Bottom Layer w15.83: D3.2 6124.99,3573.05 U6.5
U7_1: R9.2 U7.1 | length 100
  Bottom Layer w15.83: U7.1@6015,4009.05 R9.2@6015.6,3909.05
U7_2: D3.1 U7.2 | length 309.3
  Bottom Layer w15.83: U7.2@6114.99,4009.05 6054.99,3949.05 6054.99,3823.56 D3.1
U7_4: R10.2 R11.1 U7.4 | length 485.3
  Top Layer w15.83: R11.1 R10.2 6105.62,4199.68 U7.4@6214.99,4309.05
USB1_A5: R2.2 USB1.A5 | length 339.3
  Top Layer w7.91: v1(3295,4279.05) 3292.91,4279.05 3285,4286.96 3285,4318.54 3284.9,4318.64 3284.9,4335.29 3285,4335.39 3285,4356.96 3334.2,4406.16 3378.95,4406.16 3383.05,4402.06 3410.9,4402.06 3414.71,4398.25 USB1.A5@3416.8,4398.25
  Bottom Layer w7.91: R2.2 3245.63,4229.68 v1(3295,4279.05)
USB1_B5: R3.2 USB1.B5 | length 247.2
  Top Layer w7.91: v1(3315,4319.05) 3335,4319.05 3373.9,4280.15 USB1.B5@3416.83,4280.15
  Bottom Layer w7.91: R3.2 3244.37,4389.68 v1(3315,4319.05)
USB_N: U1.2 U5.13 USB1.A7 USB1.B7 | length 1802.6
  Top Layer w7.91: USB1.A7 3356.8,4339.25 3331.85,4364.2 3331.85,4375.39 v1(3339.85,4383.39) 3362.32,4383.39 3366.76,4378.95 3383.24,4378.95 3383.65,4378.55 USB1.B7
  Top Layer w10: USB1.A7 3457.34,4339.21 3459.18,4341.05 3500.99,4341.05 3507.99,4334.05 v2(3530,4334.05) ; v2(3995,3509.05) 3995,3487.04 4002,3480.04 4002,3463.41 4031.8,3433.61 4031.8,3361.1 4014.8,3344.1 U5.13
  Inner1 w10: v2(3530,4334.05) 3552.01,4334.05 3559.01,4341.05 3569.01,4341.05 3593.94,4316.12 3641.93,4316.12 3649,4309.05 3649,3901.06 4002,3548.06 4002,3538.06 3995,3531.06 v2(3995,3509.05)
  Bottom Layer w7.91: v1(3339.85,4383.39) 3349.34,4383.39 3385,4419.05 3475.48,4419.05 U1.2
USB_P: U2.2 U5.14 USB1.A6 USB1.B6 | length 1755.5
  Top Layer w7.91: v1(3363.27,4319.2) 3416.52,4319.2 USB1.B6 ; v2(3365.07,4359.12) 3365.31,4358.89 USB1.A6
  Top Layer w10: USB1.A6 3457.34,4358.89 3459.18,4357.05 3500.99,4357.05 3507.99,4364.05 v2(3530,4364.05) ; v2(4025,3509.05) 4025,3487.04 4018,3480.04 4018,3470.04 4047.8,3440.24 4047.8,3361.1 4064.8,3344.1 U5.14
  Inner1 w10: v2(3530,4364.05) 3552.01,4364.05 3559.01,4357.05 3575.64,4357.05 3600.56,4332.12 3648.56,4332.12 3665,4315.68 3665,3907.69 4018,3554.69 4018,3538.06 4025,3531.06 v2(4025,3509.05)
  Bottom Layer w7.91: v1(3363.27,4319.2) 3365.07,4321.01 v1@3365.07,4329.13 ; v2(3365.07,4359.12) v1@3365.07,4329.13 ; U2.2 3474.53,4369.05 3405,4369.05 v1@3365.07,4329.13
VBUS: C2.1 J2.1 USB1.A4 USB1.A9 USB1.B4 USB1.B9
VIN: D1.2 J1.4 | length 197.6
  Top Layer w31.61: J1.4 3605,5081.65 D1.2
VSET: C3.2 C5.2 J2.2 R6.2 U3.3 U4.3 | length 2306
  Top Layer w15.83: U3.3 C3.2@4385.6,4439.05 ; U4.3 C5.2@4385.6,4819.05 ; v1(4325,4469.05) 4325,4443.36 4329.09,4439.27 ; R6.2 v1(4445,4279.05)
  Top Layer w39.37: U3.3 4255,4519.05 4005,4519.05 3775,4749.05 3725,4749.05 3845,4869.05 4208.1,4869.05 U4.3
  Top Layer w59.05: J2.2 3725,4749.05
  Inner1 w15.83: v1(4325,4469.05) 4445,4349.05 v1(4445,4279.05)
pads on no net: OPTO1.3 OPTO1.4 RN1.4 RN2.4 SW1.2 SW1.3 SW2.2 SW2.3 SW3.2 SW3.3 TF1.1 TF1.8 TF1.9 U5.7 U5.15 U5.16 U5.22 U5.23 U5.24 U5.25 U5.26 U5.28 U5.29 U5.30 U5.32 U5.33 U5.34 U5.35 U5.36 U5.37 U5.38 U5.39 U6.1 U6.2 U6.3 U6.PE1 U6.PE2 U6.PE@ U7.3 USB1.A8 USB1.B8

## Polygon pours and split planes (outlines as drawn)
GND on Bottom Layer (solid, remove dead copper, pour order 8): 3140,5544.05 3135,3039.05 3155,3019.05 6794.99,3019.05 6824.99,3049.05 6829.99,5504.05 6789.99,5544.05
VBUS on Top Layer (solid, remove dead copper, pour order 0): 3135,4699.05 3135,4079.05 3145,4069.05 3655,4069.05 3655,4699.05
GND on Inner2 (solid, remove dead copper): 3139.08,5545.15 3134.08,3040.16 3154.08,3020.16 6794.07,3020.16 6824.07,3050.16 6829.07,5505.15 6789.07,5545.15
J2_3 on Top Layer (solid, remove dead copper, pour order 2): 3135,5339.05 3135,4799.05 3645,4799.05 3655,4809.05 3655,5319.05 3635,5339.05
+3.3V on Top Layer (solid, remove dead copper, pour order 4): 3675,4489.05 3675,4049.05 3145,4049.05 3135,4039.05 3135,3039.05 3155,3019.05 6604.99,3019.05 6634.99,3039.05 6634.99,4339.05 6624.99,4349.05 5735,4349.05 5725,4359.05 5725,5079.05 4705,5079.05 4705,4489.05
+5V on Top Layer (solid, remove dead copper, pour order 6): 6634.99,4379.05 6624.99,4369.05 5745,4369.05 5735,4379.05 5735,4399.05 5735,5089.05 4685,5089.05 4695,5079.05 4695,4509.05 4685,4499.05 4675,4499.05 3685,4499.05 3675,4509.05 3675,5319.05 3695,5339.05 6634.99,5339.05

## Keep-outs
Inner2:
  region: 3125,3999.05 3125,3299.05 3355,3299.05 3355,3999.05
Bottom Layer:
  region: 3125,3999.05 3125,3299.05 3355,3299.05 3355,3999.05 3345,3999.05
Board Outline Layer:
  circle w1: c3225,5439.05 r75
  region: 3300,5439.05 cw(c3225,5439.05) 3150,5439.05 cw(c3225,5439.05)
  circle w1: c6724.99,3139.05 r75
  region: 6799.99,3139.05 cw(c6724.99,3139.05) 6649.99,3139.05 cw(c6724.99,3139.05)
  circle w1: c3235,3139.05 r75
  region: 3310,3139.05 cw(c3235,3139.05) 3160,3139.05 cw(c3235,3139.05)
  lines w10: 3105,3078.74 ccw(c3183.74,3078.74) 3183.74,3000 6766.41,3000 ccw(c6766.41,3078.74) 6845.15,3078.74 6845.15,5480.31 ccw(c6766.41,5480.31) 6766.41,5559.05 3183.74,5559.05 ccw(c3183.74,5480.31) 3105,5480.31 3105,3078.74

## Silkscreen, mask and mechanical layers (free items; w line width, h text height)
Top Silkscreen Layer:
  text "Fiber OUT" at 5944.99,5419.05 h80
  text "GND" at 3785,5229.05 h39.37
  text "VCC" at 3785,5139.05 h39.37
  text "Install LCD at last :)" at 4095,5129.05 h80
  text "SDA" at 3785,5039.05 h39.37
  text "SCL" at 3785,4939.05 h39.37
  text "DC IN" at 3365,4829.05 h39.37
  text "PWR SET" at 3205,4639.05 h39.37 r90
  text "USB" at 3365,4629.05 h39.37
  text "AMS1117-5.0" at 3965,4629.05 h35.43 r90
  text "AMS1117-3.3" at 3965,4259.05 h35.43 r90
  text "PWR" at 4235,3969.05 h39.37
  text "3.3V" at 4235,3879.7 h39.37
  text "FB" at 4285,3779.05 h39.37
  text "LEFT" at 4294.73,3324.41 h59.05
  text "MID" at 4724.72,3324.41 h59.05
  text "RIGHT" at 5064.72,3324.41 h59.05
  text "RST" at 3825,3059.05 h39.37
  text "BOOT" at 4075,3059.05 h39.37
Bottom Silkscreen Layer:
  text "Install LCD at last :)" at 4765,5209.05 h80
Mechanical Layer:
  circle w1: c3225,5439.05 r75
  circle w1: c6724.99,3139.05 r75
  circle w1: c3235,3139.05 r75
